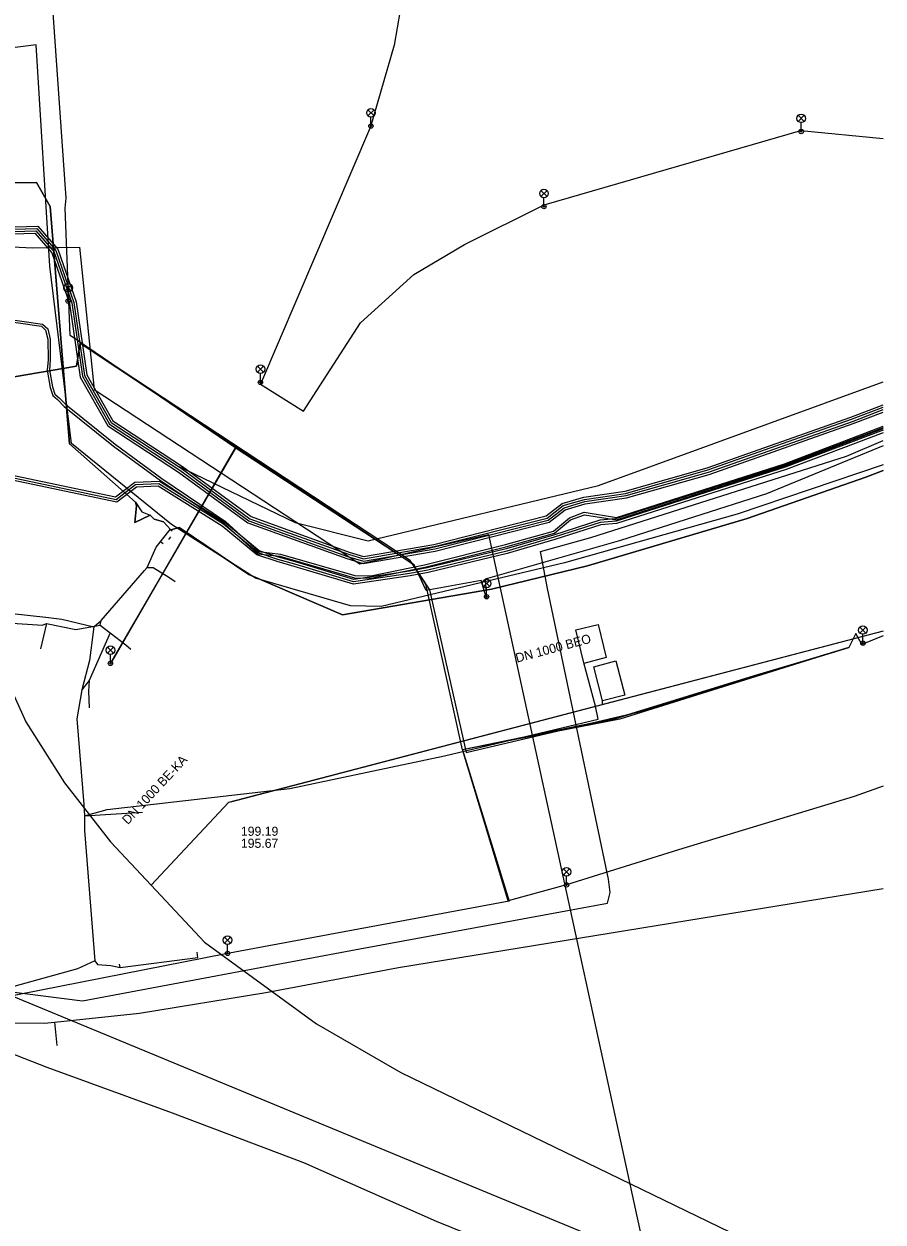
# Model space of a CAD drawing. Extents: x -598932 to -598196, y -1162210 to -1161504.
# Drawn here: x -598270.7 to -598195.6, y -1162066.4 to -1161961.6 of the extents above; entities that cross this region are included whole.
import ezdxf

# ---------------------------------------------------------------- set-up
doc = ezdxf.new("R2010")
doc.units = 0
for name, color, linetype in [('Vrstva 1', 7, 'Continuous'), ('Vrstva 12', 7, 'Continuous'), ('Vrstva 19', 7, 'Continuous'), ('Vrstva 33', 7, 'Continuous'), ('Vrstva 4', 7, 'Continuous'), ('Vrstva 42', 7, 'Continuous'), ('Vrstva 44', 7, 'Continuous'), ('Vrstva 53', 7, 'Continuous'), ('Vrstva 55', 7, 'Continuous'), ('Vrstva 58', 7, 'Continuous'), ('Vrstva 9', 7, 'Continuous')]:
    doc.layers.add(name, color=color, linetype=linetype)

msp = doc.modelspace()

# ---------------------------------------------------------------- linework, layer by layer
at = {"layer": 'Vrstva 1'}
for p, q in [((-598195.56, -1162014.715), (-598252.81, -1162029.69)), ((-598195.56, -1162014.718), (-598252.617, -1162029.642)), ((-598252.81, -1162029.69), (-598259.574, -1162036.909)), ((-598252.81, -1162029.69), (-598259.573, -1162036.91))]:
    msp.add_line(p, q, dxfattribs=at)
at = {"layer": 'Vrstva 12'}
for p, q in [((-598237.93, -1162044.09), (-598195.56, -1162037.209)), ((-598268.01, -1162048.88), (-598267.8, -1162050.92))]:
    msp.add_line(p, q, dxfattribs=at)
for points in [[(-598350.96, -1161984.4), (-598349.54, -1161985.52), (-598330.92, -1162000.49), (-598320.67, -1161999.11), (-598302.66, -1161993.97), (-598292.73, -1161992.19), (-598289.25, -1161980.43), (-598284.67, -1161980.45), (-598269.98, -1161981.19), (-598265.82, -1161981.13), (-598264.55, -1161993.58), (-598241.32, -1162008.81), (-598230.06, -1162006.26), (-598213.25, -1162083.52), (-598214.4, -1162085.15)], [(-598268.01, -1162048.88), (-598260.59, -1162048.1), (-598249.52, -1162046.28), (-598237.93, -1162044.09)], [(-598280.57, -1162048.37), (-598276.64, -1162048.94), (-598268.88, -1162048.97), (-598268.01, -1162048.88)]]:
    msp.add_lwpolyline(points, dxfattribs=at)
at = {"layer": 'Vrstva 19'}
for points in [[(-598298.4, -1162044.58), (-598297.88, -1162044.59), (-598297.12, -1162044.61), (-598280.09, -1162045.49), (-598272.45, -1162046.13), (-598265.56, -1162047.01), (-598241.63, -1162042.52), (-598219.67, -1162038.48), (-598219.41, -1162037.56), (-598219.56, -1162036.37), (-598224.9, -1162010.98), (-598225.51, -1162007.74), (-598221.12, -1162006.52), (-598198.77, -1161999.41), (-598195.56, -1161998.033)], [(-598195.56, -1162089.657), (-598208, -1162082.49), (-598220.22, -1162075.67), (-598230.34, -1162068.03), (-598234.6, -1162066.31), (-598246.2, -1162061.18), (-598257.71, -1162056.83), (-598268.65, -1162052.83), (-598280.23, -1162048.33), (-598298.02, -1162047.59), (-598299.19, -1162047.76)]]:
    msp.add_lwpolyline(points, dxfattribs=at)
at = {"layer": 'Vrstva 33'}
for p, q in [((-598240.605, -1161969.135), (-598240.075, -1161969.665)), ((-598240.605, -1161969.665), (-598240.075, -1161969.135)), ((-598240.34, -1161970.55), (-598240.34, -1161969.775)), ((-598202.985, -1161969.615), (-598202.455, -1161970.145)), ((-598202.985, -1161970.145), (-598202.455, -1161969.615)), ((-598202.72, -1161971.03), (-598202.72, -1161970.255)), ((-598225.475, -1161976.175), (-598224.945, -1161976.705)), ((-598225.475, -1161976.705), (-598224.945, -1161976.175)), ((-598225.21, -1161977.59), (-598225.21, -1161976.815)), ((-598267.085, -1161984.436), (-598266.555, -1161984.966)), ((-598267.085, -1161984.966), (-598266.555, -1161984.436)), ((-598266.82, -1161985.851), (-598266.82, -1161985.076)), ((-598250.275, -1161991.545), (-598249.745, -1161992.075)), ((-598250.275, -1161992.075), (-598249.745, -1161991.545)), ((-598250.01, -1161992.96), (-598250.01, -1161992.185)), ((-598230.489, -1162010.281), (-598229.959, -1162010.811)), ((-598230.489, -1162010.811), (-598229.959, -1162010.281)), ((-598230.224, -1162011.696), (-598230.224, -1162010.921)), ((-598197.583, -1162014.341), (-598197.053, -1162014.871)), ((-598197.583, -1162014.871), (-598197.053, -1162014.341)), ((-598197.318, -1162015.756), (-598197.318, -1162014.981)), ((-598263.385, -1162016.105), (-598262.855, -1162016.635)), ((-598263.385, -1162016.635), (-598262.855, -1162016.105)), ((-598263.12, -1162017.52), (-598263.12, -1162016.745)), ((-598223.505, -1162035.475), (-598222.975, -1162036.005)), ((-598223.505, -1162036.005), (-598222.975, -1162035.475)), ((-598223.24, -1162036.89), (-598223.24, -1162036.115)), ((-598253.145, -1162041.455), (-598252.615, -1162041.985)), ((-598253.145, -1162041.985), (-598252.615, -1162041.455)), ((-598252.88, -1162042.87), (-598252.88, -1162042.095))]:
    msp.add_line(p, q, dxfattribs=at)
for centre, radius in [((-598240.34, -1161969.4), 0.375), ((-598202.72, -1161969.88), 0.375), ((-598240.34, -1161970.55), 0.19), ((-598240.34, -1161970.55), 0.05), ((-598202.72, -1161971.03), 0.19), ((-598202.72, -1161971.03), 0.05), ((-598225.21, -1161976.44), 0.375), ((-598225.21, -1161977.59), 0.19), ((-598225.21, -1161977.59), 0.05), ((-598266.82, -1161984.701), 0.375), ((-598266.82, -1161985.851), 0.19), ((-598266.82, -1161985.851), 0.05), ((-598250.01, -1161991.81), 0.375), ((-598250.01, -1161992.96), 0.19), ((-598250.01, -1161992.96), 0.05), ((-598230.224, -1162010.546), 0.375), ((-598230.224, -1162011.696), 0.19), ((-598230.224, -1162011.696), 0.05), ((-598197.318, -1162014.606), 0.375), ((-598263.12, -1162016.37), 0.375), ((-598197.318, -1162015.756), 0.19), ((-598197.318, -1162015.756), 0.05), ((-598263.12, -1162017.52), 0.19), ((-598263.12, -1162017.52), 0.05), ((-598223.24, -1162035.74), 0.375), ((-598223.24, -1162036.89), 0.19), ((-598223.24, -1162036.89), 0.05), ((-598252.88, -1162041.72), 0.375), ((-598252.88, -1162042.87), 0.19), ((-598252.88, -1162042.87), 0.05)]:
    msp.add_circle(centre, radius, dxfattribs=at)
at = {"layer": 'Vrstva 42'}
for p, q in [((-598257.83, -1162005.84), (-598257.724, -1162005.97)), ((-598257.885, -1162006.464), (-598258.047, -1162006.696)), ((-598258.525, -1162007.07), (-598258.746, -1162006.9)), ((-598258.02, -1162009.97), (-598257.46, -1162010.37)), ((-598268.71, -1162014.04), (-598269.25, -1162016.26)), ((-598264.01, -1162014.18), (-598263.92, -1162013.77)), ((-598264.01, -1162014.18), (-598263.14, -1162014.84)), ((-598263.14, -1162014.84), (-598264.99, -1162019.03)), ((-598263.14, -1162014.84), (-598261.79, -1162015.89)), ((-598261.79, -1162015.89), (-598261.34, -1162016.27)), ((-598264.99, -1162019.03), (-598265.61, -1162019.84)), ((-598264.99, -1162019.03), (-598265.05, -1162019.96)), ((-598265.05, -1162019.96), (-598264.99, -1162021.42)), ((-598263.08, -1162043.93), (-598262.27, -1162044.09)), ((-598262.27, -1162044.09), (-598262.34, -1162043.82))]:
    msp.add_line(p, q, dxfattribs=at)
for points in [[(-598285.31, -1161975.6), (-598269.59, -1161975.5), (-598268.4, -1161977.59), (-598267.37, -1161990.2), (-598266.69, -1161998.34), (-598260.93, -1162003.44), (-598260.37, -1162004.28), (-598259.64, -1162004.57), (-598259.29, -1162004.9), (-598258.48, -1162005.16), (-598257.83, -1162005.84), (-598257.12, -1162005.65), (-598251.01, -1162009.76), (-598242.82, -1162013.28), (-598229.8, -1162011.04), (-598221.4, -1162008.98), (-598207.45, -1162004.87), (-598197.06, -1162001.25), (-598195.56, -1162000.659)], [(-598260.93, -1162003.44), (-598260.83, -1162003.75), (-598261, -1162005.21), (-598259.64, -1162004.57)], [(-598259.91, -1162009.13), (-598259.11, -1162007.375), (-598257.909, -1162005.813), (-598257.715, -1162005.94)], [(-598263.92, -1162013.77), (-598260.134, -1162009.391), (-598259.91, -1162009.13)], [(-598259.91, -1162009.13), (-598259.39, -1162009.15), (-598258.02, -1162009.97)], [(-598280.62, -1162014.39), (-598277.643, -1162012.515), (-598268.768, -1162013.491), (-598267.381, -1162013.661), (-598264.563, -1162014.319), (-598263.92, -1162013.77)], [(-598286.94, -1162015.46), (-598281.22, -1162014.88), (-598274.83, -1162013.8), (-598269.05, -1162014.17), (-598268.71, -1162014.04)], [(-598268.71, -1162014.04), (-598266.14, -1162014.57), (-598264.01, -1162014.18)], [(-598220.72, -1162021.27), (-598221.73, -1162017.46), (-598222.433, -1162014.6), (-598220.48, -1162014.12), (-598219.77, -1162017.01), (-598221.713, -1162017.525)], [(-598264.563, -1162014.319), (-598264.95, -1162017.267), (-598265.61, -1162019.84), (-598266.05, -1162022.38), (-598265.449, -1162029.865), (-598265.4, -1162030.84), (-598260.31, -1162030.52)], [(-598220.09, -1162020.79), (-598220.85, -1162017.83), (-598218.92, -1162017.3), (-598218.152, -1162020.292), (-598220.09, -1162020.79)], [(-598265.4, -1162030.84), (-598263.4, -1162030.29), (-598247.43, -1162028.45), (-598233.92, -1162025.61), (-598220.47, -1162022.4), (-598220.72, -1162021.27)], [(-598220.72, -1162021.27), (-598220.08, -1162021.1), (-598220.09, -1162020.79)], [(-598265.4, -1162030.84), (-598265.38, -1162032.14), (-598264.5, -1162043.53)], [(-598264.5, -1162043.53), (-598266.01, -1162044.23), (-598272.1, -1162045.9), (-598278.52, -1162047.22), (-598286.93, -1162048.62), (-598287.83, -1162043.38)], [(-598264.5, -1162043.53), (-598264.24, -1162043.83), (-598263.08, -1162043.93)], [(-598262.27, -1162044.09), (-598255.49, -1162043.22), (-598255.54, -1162042.75)]]:
    msp.add_lwpolyline(points, dxfattribs=at)
at = {"layer": 'Vrstva 44'}
for points in [[(-598276.428, -1161979.72), (-598269.566, -1161979.519), (-598267.902, -1161981.429), (-598266.312, -1161985.966), (-598265.384, -1161992.357), (-598263.055, -1161996.47), (-598256.933, -1162000.468), (-598250.923, -1162004.871), (-598242.318, -1162007.975), (-598240.994, -1162008.377), (-598234.801, -1162007.312), (-598224.935, -1162004.818), (-598223.537, -1162003.73), (-598221.681, -1162003.182), (-598218.071, -1162002.662), (-598210.88, -1162000.615), (-598198.305, -1161996.186), (-598195.56, -1161995.124)], [(-598276.422, -1161979.52), (-598269.477, -1161979.316), (-598267.726, -1161981.326), (-598266.117, -1161985.918), (-598265.191, -1161992.291), (-598262.905, -1161996.329), (-598256.819, -1162000.303), (-598250.828, -1162004.692), (-598242.255, -1162007.785), (-598240.981, -1162008.172), (-598234.842, -1162007.116), (-598225.025, -1162004.635), (-598223.629, -1162003.548), (-598221.724, -1162002.986), (-598218.113, -1162002.466), (-598210.941, -1162000.424), (-598198.374, -1161995.999), (-598195.56, -1161994.911)], [(-598276.438, -1161980.12), (-598269.743, -1161979.924), (-598268.254, -1161981.634), (-598266.703, -1161986.062), (-598265.769, -1161992.489), (-598263.355, -1161996.751), (-598257.161, -1162000.797), (-598251.112, -1162005.228), (-598242.445, -1162008.355), (-598241.019, -1162008.788), (-598234.718, -1162007.704), (-598224.755, -1162005.185), (-598223.351, -1162004.092), (-598221.596, -1162003.574), (-598217.987, -1162003.054), (-598210.759, -1162000.996), (-598198.166, -1161996.561), (-598195.56, -1161995.553)], [(-598276.433, -1161979.92), (-598269.654, -1161979.721), (-598268.078, -1161981.531), (-598266.508, -1161986.014), (-598265.576, -1161992.423), (-598263.205, -1161996.611), (-598257.047, -1162000.632), (-598251.017, -1162005.049), (-598242.382, -1162008.165), (-598241.006, -1162008.583), (-598234.759, -1162007.508), (-598224.845, -1162005.002), (-598223.444, -1162003.911), (-598221.639, -1162003.378), (-598218.029, -1162002.858), (-598210.82, -1162000.805), (-598198.235, -1161996.374), (-598195.56, -1161995.339)], [(-598296.362, -1161984.109), (-598269.146, -1161988.044), (-598268.791, -1161988.382), (-598268.6, -1161989.192), (-598268.58, -1161990.987), (-598268.651, -1161991.895), (-598268.387, -1161993.394), (-598268.157, -1161994.107), (-598267.759, -1161994.463), (-598267.167, -1161995.055), (-598262.841, -1161998.529), (-598258.758, -1162001.532), (-598253.172, -1162005.279), (-598250.253, -1162007.946), (-598248.299, -1162008.158), (-598241.785, -1162010.04), (-598240.341, -1162010.07), (-598235.628, -1162009.108), (-598228.534, -1162007.337), (-598224.293, -1162006.131), (-598222.879, -1162004.978), (-598221.679, -1162004.523), (-598218.862, -1162004.962), (-598204.117, -1162000.264), (-598195.56, -1161996.994)], [(-598296.338, -1161983.911), (-598269.054, -1161987.856), (-598268.609, -1161988.278), (-598268.4, -1161989.168), (-598268.38, -1161990.993), (-598268.449, -1161991.885), (-598268.193, -1161993.346), (-598267.983, -1161993.993), (-598267.621, -1161994.317), (-598267.033, -1161994.905), (-598262.719, -1161998.371), (-598258.642, -1162001.368), (-598253.048, -1162005.121), (-598250.167, -1162007.754), (-598248.261, -1162007.962), (-598241.755, -1162009.84), (-598240.359, -1162009.87), (-598235.672, -1162008.912), (-598228.586, -1162007.143), (-598224.387, -1162005.949), (-598222.981, -1162004.802), (-598221.701, -1162004.317), (-598218.878, -1162004.758), (-598204.183, -1162000.076), (-598195.56, -1161996.781)]]:
    msp.add_lwpolyline(points, dxfattribs=at)
at = {"layer": 'Vrstva 53'}
for points in [[(-598195.56, -1162000.162), (-598208.32, -1162004.49), (-598223.41, -1162008.73), (-598239.46, -1162012.56), (-598242.13, -1162012.49), (-598250.45, -1162010.07), (-598257.78, -1162005.38), (-598266.53, -1161998.3), (-598268.41, -1161982.8), (-598269.61, -1161963.44), (-598286.96, -1161965.68)], [(-598257.44, -1162000.16), (-598246.98, -1162005.2), (-598240.58, -1162006.81), (-598220.43, -1162001.97), (-598195.56, -1161992.919)]]:
    msp.add_lwpolyline(points, dxfattribs=at)
at = {"layer": 'Vrstva 55'}
for points in [[(-598266.98, -1161976.87), (-598269.342, -1161943.181), (-598268.89, -1161928.63), (-598266.36, -1161902.083), (-598263.633, -1161891.659)], [(-598251.295, -1161892.852), (-598251.209, -1161892.945), (-598248.78, -1161900.2), (-598240.532, -1161920.329), (-598238.05, -1161929.16), (-598235.1, -1161940.43), (-598235.423, -1161946.778), (-598238.32, -1161963.49), (-598240.392, -1161970.621), (-598249.997, -1161993.104), (-598246.244, -1161995.469), (-598241.254, -1161987.753), (-598236.581, -1161983.526), (-598232.15, -1161980.92), (-598225.184, -1161977.447), (-598202.751, -1161970.948), (-598195.56, -1161971.654)], [(-598252.16, -1161998.72), (-598266.655, -1161988.86), (-598267.08, -1161977.73), (-598266.98, -1161976.87)], [(-598198.55, -1162016.13), (-598205.58, -1162018.27), (-598219.03, -1162022.39), (-598232.33, -1162025.07), (-598235.53, -1162010.6), (-598236.9, -1162008.54), (-598265.78, -1161989.54), (-598266.09, -1161991.53), (-598291.82, -1161995.93), (-598293.65, -1161997.61), (-598298.2, -1162001.02), (-598304.153, -1162004.313), (-598309.864, -1162006.381), (-598314.688, -1162006.922), (-598320.694, -1162006.036), (-598325.72, -1162004.7), (-598330.78, -1162002.36), (-598332.57, -1162000.21), (-598351.13, -1161984.79)], [(-598291.82, -1161995.93), (-598266.09, -1161991.53), (-598265.78, -1161989.54), (-598236.75, -1162008.79), (-598235.22, -1162011.09), (-598232.01, -1162025.3), (-598217.04, -1162021.78), (-598198.55, -1162016.13)], [(-598195.56, -1161998.491), (-598205.74, -1162002.69), (-598218.51, -1162006.77), (-598230.352, -1162010.157), (-598230.224, -1162011.824), (-598230.694, -1162010.285), (-598235.5, -1162011.15), (-598236.56, -1162008.91), (-598238.26, -1162007.82), (-598252.22, -1161998.67), (-598263.07, -1162017.43), (-598252.16, -1161998.72)], [(-598195.56, -1162015.123), (-598197.42, -1162015.86), (-598197.94, -1162014.91), (-598198.55, -1162016.13)], [(-598198.55, -1162016.13), (-598218.57, -1162022.39), (-598232.33, -1162025.07), (-598228.247, -1162038.308), (-598253.04, -1162042.9), (-598274.69, -1162047.15), (-598287.68, -1162049.37), (-598288.731, -1162041.553), (-598292.452, -1162042.269), (-598295.111, -1162042.693)], [(-598195.56, -1162028.248), (-598198.09, -1162029.16), (-598213.46, -1162033.82), (-598223.24, -1162036.89), (-598228.336, -1162038.264), (-598232.35, -1162025.04), (-598218.72, -1162022.24), (-598206.8, -1162018.57), (-598198.55, -1162016.13)]]:
    msp.add_lwpolyline(points, dxfattribs=at)
at = {"layer": 'Vrstva 58'}
for points in [[(-598261, -1162005.21), (-598260.83, -1162003.75), (-598260.93, -1162003.44), (-598266.69, -1161998.34), (-598267.37, -1161990.2), (-598268.4, -1161977.59), (-598269.59, -1161975.5), (-598285.31, -1161975.6), (-598286.33, -1161980.19), (-598288.62, -1161987.13), (-598290.58, -1161992.26), (-598292.47, -1161995.23), (-598296.85, -1161996.28), (-598306.68, -1161999.03), (-598307.78, -1161999.13)], [(-598195.56, -1161996.929), (-598204.176, -1162000.191), (-598218.949, -1162004.892), (-598220.329, -1162005.002), (-598224.379, -1162006.299), (-598228.522, -1162007.517), (-598235.422, -1162009.174), (-598236.973, -1162009.463), (-598241.845, -1162010.186), (-598246.934, -1162008.658), (-598248.421, -1162008.239), (-598250.111, -1162007.672), (-598253.113, -1162005.197), (-598258.837, -1162001.627), (-598260.992, -1162001.723), (-598262.669, -1162003.005), (-598293.519, -1161996.518), (-598300.123, -1161993.635), (-598305.947, -1161991.318)], [(-598195.56, -1161997.357), (-598204.044, -1162000.569), (-598218.871, -1162005.288), (-598220.251, -1162005.398), (-598224.261, -1162006.681), (-598228.418, -1162007.903), (-598235.338, -1162009.566), (-598236.907, -1162009.857), (-598241.875, -1162010.594), (-598247.046, -1162009.042), (-598248.539, -1162008.621), (-598250.309, -1162008.028), (-598253.347, -1162005.523), (-598258.943, -1162002.033), (-598260.848, -1162002.117), (-598262.571, -1162003.435), (-598293.641, -1161996.902)], [(-598195.56, -1161997.143), (-598204.11, -1162000.38), (-598218.91, -1162005.09), (-598220.29, -1162005.2), (-598224.32, -1162006.49), (-598228.47, -1162007.71), (-598235.38, -1162009.37), (-598236.94, -1162009.66), (-598241.86, -1162010.39), (-598246.99, -1162008.85), (-598248.48, -1162008.43), (-598250.21, -1162007.85), (-598253.23, -1162005.36), (-598258.89, -1162001.83), (-598260.92, -1162001.92), (-598262.62, -1162003.22), (-598293.58, -1161996.71)], [(-598195.56, -1161997.143), (-598204.11, -1162000.38), (-598218.91, -1162005.09), (-598220.29, -1162005.2), (-598224.32, -1162006.49), (-598228.47, -1162007.71), (-598235.38, -1162009.37), (-598236.94, -1162009.66), (-598241.86, -1162010.39), (-598246.99, -1162008.85), (-598248.48, -1162008.43), (-598250.21, -1162007.85), (-598253.23, -1162005.36), (-598258.89, -1162001.83), (-598260.92, -1162001.92), (-598262.62, -1162003.22), (-598293.58, -1161996.71)], [(-598195.56, -1161996.929), (-598204.176, -1162000.191), (-598218.949, -1162004.892), (-598220.329, -1162005.002), (-598224.379, -1162006.299), (-598228.522, -1162007.517), (-598235.422, -1162009.174), (-598236.973, -1162009.463), (-598241.845, -1162010.186), (-598246.934, -1162008.658), (-598248.421, -1162008.239), (-598250.111, -1162007.672), (-598253.113, -1162005.197), (-598258.837, -1162001.627), (-598260.992, -1162001.723), (-598262.669, -1162003.005), (-598293.519, -1161996.518)], [(-598195.56, -1162000.659), (-598197.06, -1162001.25), (-598207.45, -1162004.87), (-598221.4, -1162008.98), (-598229.8, -1162011.04), (-598242.82, -1162013.28), (-598251.01, -1162009.76), (-598257.12, -1162005.65), (-598257.83, -1162005.84), (-598258.48, -1162005.16), (-598259.29, -1162004.9), (-598259.64, -1162004.57), (-598261, -1162005.21)], [(-598260.93, -1162003.44), (-598260.83, -1162003.75), (-598261, -1162005.21), (-598259.64, -1162004.57)]]:
    msp.add_lwpolyline(points, dxfattribs=at)
at = {"layer": 'Vrstva 9'}
for points in [[(-598279.587, -1161995.435), (-598278.63, -1162000.737), (-598277.149, -1162006.504), (-598274.962, -1162012.832), (-598270.519, -1162022.621), (-598267.15, -1162027.964), (-598263.128, -1162033.13), (-598259.574, -1162036.909)], [(-598259.574, -1162036.909), (-598254.887, -1162041.893), (-598245.096, -1162049.021), (-598237.728, -1162053.27)], [(-598273.666, -1162045.789), (-598211.238, -1162071.616), (-598195.56, -1162078.528)], [(-598237.728, -1162053.27), (-598209, -1162067.221), (-598195.56, -1162078.081)]]:
    msp.add_lwpolyline(points, dxfattribs=at)

# ---------------------------------------------------------------- texts
at = {"layer": 'Vrstva 4'}
for s, rotation, p in [('DN 1000 BEO', 15, (-598227.576, -1162017.46)), ('DN 1000 BE-KA', 47, (-598261.603, -1162031.659))]:
    msp.add_text(s, height=0.8, rotation=rotation, dxfattribs=at).set_placement(p)
for s, p in [('199.19', (-598251.713, -1162032.592)), ('195.67', (-598251.713, -1162033.642))]:
    msp.add_text(s, height=0.8, dxfattribs=at).set_placement(p)

doc.saveas('drawing.dxf')
